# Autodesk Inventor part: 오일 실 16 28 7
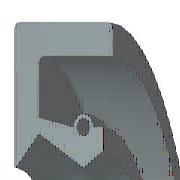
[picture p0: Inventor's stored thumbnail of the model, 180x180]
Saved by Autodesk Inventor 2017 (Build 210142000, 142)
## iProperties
Created: 2012-02
Part Number: 오일 실 16 28 7
Material: 고무
Description: 오일-실
Document SubType Name: Modeling
Standard: KS B 2804
Designer: mduedu
Standards Organization: KS
Language: ko-KR
Size Designation: D - 16 28 7
Categories: <MemberInstance><Categories><Category DisplayName="샤프트 부품" InternalName="7f7aeb1f-a693-4053-b835-cee3144e0d98" Mnemonic="SHFT"><Category DisplayName="실링" Intern
Density: 0.93 g/cm^3
Appearance: 고무 - 검은색 - 버전 1.1
IsCustomPart: 1
Author: mduedu
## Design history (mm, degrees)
revolve "본체" stored, may be unused: angle "d17" = 90 deg
revolve "스프링1" stored, may be unused: angle "d18" = 90 deg
fillet "모깎기3" dims "d43" = 0.5
body "Solid1"
sketch "스케치1"
  geometry: L1 (0, 14)-(7, 14); L2 (7, 12.25)-(1.75, 12.25); L3 (1.75, 9.75)-(4.9, 8); L4 (4.9, 8)-(0, 8); L5 (0, 0)-(9.586, 0) reference; L6 (4.9, 8)-(6.3, 8.875); L7 (0, 18)-(0, -3) reference; L8 (-1.941, 0)-(11.507, 0) reference; L9 (4.2, 10.1)-(1.75, 10.59); L10 (1.75, 10.59)-(1.75, 12.25); L11 (0, 14)-(0, 8.088); L12 (4.9, 8)-(0, 8); L13 (1.75, 9.75)-(0.152, 8.028); L14 (7, 14)-(7, 12.25); L15 (5.6, 10.1)-(6.3, 10.1); L16 (6.3, 10.1)-(6.3, 8.875); C1 r 0.455 at (4.9, 10.1); A1 r 0.7 centre (4.9, 10.1) between (5.6, 10.1) and (4.2, 10.1); A2 r 0.088 centre (0.088, 8.088) between (0, 8.088) and (0.152, 8.028); 1 further point
  constraints: 28 end point, 5 horizontal alignment, 5 point on line, 4 point on circle, 4 vertical alignment, 3 centre point, 3 tangent, 2 collinear, 2 horizontal, 2 perpendicular, 1 coincident, 1 parallel
  dimensions: "d0" = 28 diameter of L1 L5 (= SD2); "d1" = 1.75 distance of L1.end L2.start (= SD); "d2" = 0.91 diameter of C1 (= SPDI); "d3" = 1.4 diameter of A1 (= SPDA); "d4" = 16 diameter of L3.end L5 (= NND); "d5" = 19.5 diameter of L3.start L5 (= TKDM); "d7" = 21.18 diameter of L9.end L5 (= TKDM + 0.24 x SWDT); "d8" = 1.75 distance between parallel lines of L11 L10 (= SD); "d9" = 4.9 distance from line of L11 C1.centre (= SPDST); "d10" = 20.2 diameter of C1.centre L5 (= HLDM); "d11" = 0.0875 radius of A2 (= 0.25 x LAB); "d12" = 6.3 distance between parallel lines of L11 L16 (= SDI); "d13" = 17.75 diameter of L6.end L5 (= ABDM); "d14" = 7 distance from line of L11 L1.end (= SWDT)
fillet "모깎기1" dims "d6" = 0.3 (= RR)
other parameters: "SD2" = 28 [user parameter; used in 1 equation term], "SWDT" = 7 [user parameter; used in 2 equation terms], "RR" = 0.3 [user parameter; used in 1 equation term], "SD" = 1.75 [user parameter; used in 2 equation terms], "NND" = 16 [user parameter; used in 1 equation term], "SPDA" = 1.4 [user parameter; used in 1 equation term], "SPDI" = 0.91 [user parameter; used in 1 equation term], "TKDM" = 19.5 [user parameter; used in 2 equation terms], "HLDM" = 20.2 [user parameter; used in 1 equation term], "ABDM" = 17.75 [user parameter; used in 1 equation term], "SDI" = 6.3 [user parameter; used in 1 equation term], "SPDST" = 4.9 [user parameter; used in 1 equation term], "LAB" = 0.35 [user parameter; used in 1 equation term], "d15" = 0, "d16" = 0, "d19" = 0
